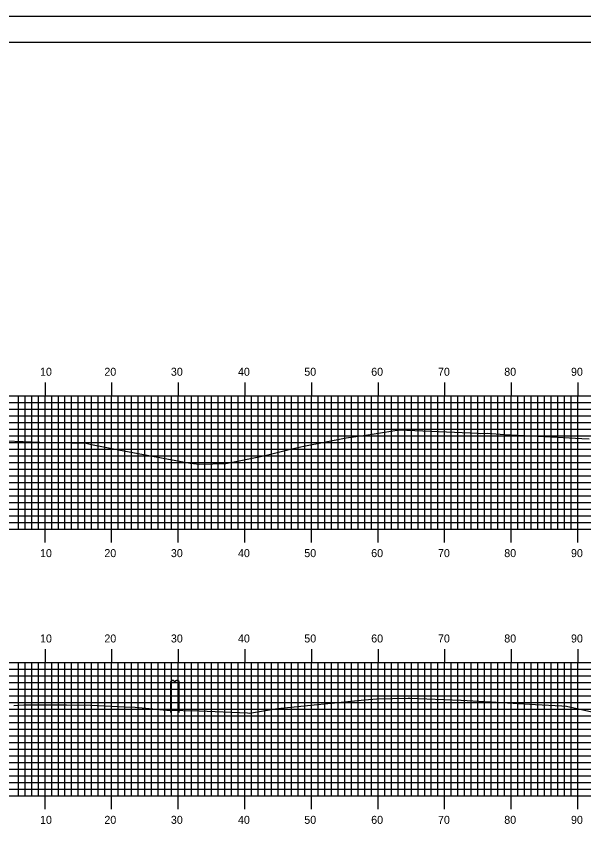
# Model space of a CAD drawing. Extents: x 855074 to 855418, y 366605 to 366825.
# Drawn here: x 855245.8 to 855330.9, y 366701.1 to 366824.9 of the extents above; entities that cross this region are included whole.
import ezdxf

# ---------------------------------------------------------------- set-up
doc = ezdxf.new("R2010")
doc.units = 0
for name, color, linetype in [('BORDER', 7, 'Continuous'), ('H_V ANNOTATION', 7, 'Continuous'), ('M_Roadway_Centerline', 7, 'Continuous'), ('MAJOR', 7, 'Continuous'), ('MINOR', 7, 'Continuous'), ('PLOT BOUNDARY', 7, 'Continuous'), ('S_Roadway_Centerline', 7, 'Continuous'), ('S_Utilities_Pole_StreetLight', 7, 'Continuous')]:
    doc.layers.add(name, color=color, linetype=linetype)

msp = doc.modelspace()

# ---------------------------------------------------------------- linework, layer by layer
at = {"layer": 'BORDER'}
msp.add_lwpolyline([(855090.47, 366611.06), (855410.47, 366611.06), (855410.47, 366821.06), (855090.47, 366821.06)], close=True, dxfattribs=at)
at = {"layer": 'MAJOR'}
for p, q in [((855250.07, 366770.06), (855250.07, 366768.06)), ((855260.07, 366770.06), (855260.07, 366768.06)), ((855270.07, 366770.06), (855270.07, 366768.06)), ((855280.07, 366770.06), (855280.07, 366768.06)), ((855290.07, 366770.06), (855290.07, 366768.06)), ((855300.07, 366770.06), (855300.07, 366768.06)), ((855310.07, 366770.06), (855310.07, 366768.06)), ((855320.07, 366770.06), (855320.07, 366768.06)), ((855330.07, 366770.06), (855330.07, 366768.06)), ((855100.07, 366768.06), (855380.07, 366768.06)), ((855100.07, 366768.06), (855380.07, 366768.06)), ((855250.07, 366748.06), (855250.07, 366768.06)), ((855260.07, 366748.06), (855260.07, 366768.06)), ((855270.07, 366748.06), (855270.07, 366768.06)), ((855280.07, 366748.06), (855280.07, 366768.06)), ((855290.07, 366748.06), (855290.07, 366768.06)), ((855300.07, 366748.06), (855300.07, 366768.06)), ((855310.07, 366748.06), (855310.07, 366768.06)), ((855320.07, 366748.06), (855320.07, 366768.06)), ((855330.07, 366748.06), (855330.07, 366768.06)), ((855100.07, 366763.06), (855380.07, 366763.06)), ((855100.07, 366758.06), (855380.07, 366758.06)), ((855100.07, 366753.06), (855380.07, 366753.06)), ((855100.07, 366748.06), (855380.07, 366748.06)), ((855100.07, 366748.06), (855380.07, 366748.06)), ((855250.07, 366746.05), (855250.07, 366748.06)), ((855260.07, 366746.05), (855260.07, 366748.06)), ((855270.07, 366746.05), (855270.07, 366748.06)), ((855280.07, 366746.05), (855280.07, 366748.06)), ((855290.07, 366746.05), (855290.07, 366748.06)), ((855300.07, 366746.05), (855300.07, 366748.06)), ((855310.07, 366746.05), (855310.07, 366748.06)), ((855320.07, 366746.05), (855320.07, 366748.06)), ((855330.07, 366746.05), (855330.07, 366748.06)), ((855250.07, 366730.06), (855250.07, 366728.06)), ((855260.07, 366730.06), (855260.07, 366728.06)), ((855270.07, 366730.06), (855270.07, 366728.06)), ((855280.07, 366730.06), (855280.07, 366728.06)), ((855290.07, 366730.06), (855290.07, 366728.06)), ((855300.07, 366730.06), (855300.07, 366728.06)), ((855310.07, 366730.06), (855310.07, 366728.06)), ((855320.07, 366730.06), (855320.07, 366728.06)), ((855330.07, 366730.06), (855330.07, 366728.06)), ((855100.07, 366728.06), (855380.07, 366728.06)), ((855100.07, 366728.06), (855380.07, 366728.06)), ((855250.07, 366708.06), (855250.07, 366728.06)), ((855260.07, 366708.06), (855260.07, 366728.06)), ((855270.07, 366708.06), (855270.07, 366728.06)), ((855280.07, 366708.06), (855280.07, 366728.06)), ((855290.07, 366708.06), (855290.07, 366728.06)), ((855300.07, 366708.06), (855300.07, 366728.06)), ((855310.07, 366708.06), (855310.07, 366728.06)), ((855320.07, 366708.06), (855320.07, 366728.06)), ((855330.07, 366708.06), (855330.07, 366728.06)), ((855100.07, 366723.06), (855380.07, 366723.06)), ((855100.07, 366718.06), (855380.07, 366718.06)), ((855100.07, 366713.06), (855380.07, 366713.06)), ((855100.07, 366708.06), (855380.07, 366708.06)), ((855100.07, 366708.06), (855380.07, 366708.06)), ((855250.07, 366706.05), (855250.07, 366708.06)), ((855260.07, 366706.05), (855260.07, 366708.06)), ((855270.07, 366706.05), (855270.07, 366708.06)), ((855280.07, 366706.05), (855280.07, 366708.06)), ((855290.07, 366706.05), (855290.07, 366708.06)), ((855300.07, 366706.05), (855300.07, 366708.06)), ((855310.07, 366706.05), (855310.07, 366708.06)), ((855320.07, 366706.05), (855320.07, 366708.06)), ((855330.07, 366706.05), (855330.07, 366708.06))]:
    msp.add_line(p, q, dxfattribs=at)
at = {"layer": 'MINOR'}
for p, q in [((855246.07, 366748.06), (855246.07, 366768.06)), ((855247.07, 366748.06), (855247.07, 366768.06)), ((855248.07, 366748.06), (855248.07, 366768.06)), ((855249.07, 366748.06), (855249.07, 366768.06)), ((855251.07, 366748.06), (855251.07, 366768.06)), ((855252.07, 366748.06), (855252.07, 366768.06)), ((855253.07, 366748.06), (855253.07, 366768.06)), ((855254.07, 366748.06), (855254.07, 366768.06)), ((855255.07, 366748.06), (855255.07, 366768.06)), ((855256.07, 366748.06), (855256.07, 366768.06)), ((855257.07, 366748.06), (855257.07, 366768.06)), ((855258.07, 366748.06), (855258.07, 366768.06)), ((855259.07, 366748.06), (855259.07, 366768.06)), ((855261.07, 366748.06), (855261.07, 366768.06)), ((855262.07, 366748.06), (855262.07, 366768.06)), ((855263.07, 366748.06), (855263.07, 366768.06)), ((855264.07, 366748.06), (855264.07, 366768.06)), ((855265.07, 366748.06), (855265.07, 366768.06)), ((855266.07, 366748.06), (855266.07, 366768.06)), ((855267.07, 366748.06), (855267.07, 366768.06)), ((855268.07, 366748.06), (855268.07, 366768.06)), ((855269.07, 366748.06), (855269.07, 366768.06)), ((855271.07, 366748.06), (855271.07, 366768.06)), ((855272.07, 366748.06), (855272.07, 366768.06)), ((855273.07, 366748.06), (855273.07, 366768.06)), ((855274.07, 366748.06), (855274.07, 366768.06)), ((855275.07, 366748.06), (855275.07, 366768.06)), ((855276.07, 366748.06), (855276.07, 366768.06)), ((855277.07, 366748.06), (855277.07, 366768.06)), ((855278.07, 366748.06), (855278.07, 366768.06)), ((855279.07, 366748.06), (855279.07, 366768.06)), ((855281.07, 366748.06), (855281.07, 366768.06)), ((855282.07, 366748.06), (855282.07, 366768.06)), ((855283.07, 366748.06), (855283.07, 366768.06)), ((855284.07, 366748.06), (855284.07, 366768.06)), ((855285.07, 366748.06), (855285.07, 366768.06)), ((855286.07, 366748.06), (855286.07, 366768.06)), ((855287.07, 366748.06), (855287.07, 366768.06)), ((855288.07, 366748.06), (855288.07, 366768.06)), ((855289.07, 366748.06), (855289.07, 366768.06)), ((855291.07, 366748.06), (855291.07, 366768.06)), ((855292.07, 366748.06), (855292.07, 366768.06)), ((855293.07, 366748.06), (855293.07, 366768.06)), ((855294.07, 366748.06), (855294.07, 366768.06)), ((855295.07, 366748.06), (855295.07, 366768.06)), ((855296.07, 366748.06), (855296.07, 366768.06)), ((855297.07, 366748.06), (855297.07, 366768.06)), ((855298.07, 366748.06), (855298.07, 366768.06)), ((855299.07, 366748.06), (855299.07, 366768.06)), ((855301.07, 366748.06), (855301.07, 366768.06)), ((855302.07, 366748.06), (855302.07, 366768.06)), ((855303.07, 366748.06), (855303.07, 366768.06)), ((855304.07, 366748.06), (855304.07, 366768.06)), ((855305.07, 366748.06), (855305.07, 366768.06)), ((855306.07, 366748.06), (855306.07, 366768.06)), ((855307.07, 366748.06), (855307.07, 366768.06)), ((855308.07, 366748.06), (855308.07, 366768.06)), ((855309.07, 366748.06), (855309.07, 366768.06)), ((855311.07, 366748.06), (855311.07, 366768.06)), ((855312.07, 366748.06), (855312.07, 366768.06)), ((855313.07, 366748.06), (855313.07, 366768.06)), ((855314.07, 366748.06), (855314.07, 366768.06)), ((855315.07, 366748.06), (855315.07, 366768.06)), ((855316.07, 366748.06), (855316.07, 366768.06)), ((855317.07, 366748.06), (855317.07, 366768.06)), ((855318.07, 366748.06), (855318.07, 366768.06)), ((855319.07, 366748.06), (855319.07, 366768.06)), ((855321.07, 366748.06), (855321.07, 366768.06)), ((855322.07, 366748.06), (855322.07, 366768.06)), ((855323.07, 366748.06), (855323.07, 366768.06)), ((855324.07, 366748.06), (855324.07, 366768.06)), ((855325.07, 366748.06), (855325.07, 366768.06)), ((855326.07, 366748.06), (855326.07, 366768.06)), ((855327.07, 366748.06), (855327.07, 366768.06)), ((855328.07, 366748.06), (855328.07, 366768.06)), ((855329.07, 366748.06), (855329.07, 366768.06)), ((855100.07, 366767.06), (855380.07, 366767.06)), ((855100.07, 366766.06), (855380.07, 366766.06)), ((855100.07, 366765.06), (855380.07, 366765.06)), ((855100.07, 366764.06), (855380.07, 366764.06)), ((855100.07, 366762.06), (855380.07, 366762.06)), ((855100.07, 366761.06), (855380.07, 366761.06)), ((855100.07, 366760.06), (855380.07, 366760.06)), ((855100.07, 366759.06), (855380.07, 366759.06)), ((855100.07, 366757.06), (855380.07, 366757.06)), ((855100.07, 366756.06), (855380.07, 366756.06)), ((855100.07, 366755.06), (855380.07, 366755.06)), ((855100.07, 366754.06), (855380.07, 366754.06)), ((855100.07, 366752.06), (855380.07, 366752.06)), ((855100.07, 366751.06), (855380.07, 366751.06)), ((855100.07, 366750.06), (855380.07, 366750.06)), ((855100.07, 366749.06), (855380.07, 366749.06)), ((855246.07, 366708.06), (855246.07, 366728.06)), ((855247.07, 366708.06), (855247.07, 366728.06)), ((855248.07, 366708.06), (855248.07, 366728.06)), ((855249.07, 366708.06), (855249.07, 366728.06)), ((855251.07, 366708.06), (855251.07, 366728.06)), ((855252.07, 366708.06), (855252.07, 366728.06)), ((855253.07, 366708.06), (855253.07, 366728.06)), ((855254.07, 366708.06), (855254.07, 366728.06)), ((855255.07, 366708.06), (855255.07, 366728.06)), ((855256.07, 366708.06), (855256.07, 366728.06)), ((855257.07, 366708.06), (855257.07, 366728.06)), ((855258.07, 366708.06), (855258.07, 366728.06)), ((855259.07, 366708.06), (855259.07, 366728.06)), ((855261.07, 366708.06), (855261.07, 366728.06)), ((855262.07, 366708.06), (855262.07, 366728.06)), ((855263.07, 366708.06), (855263.07, 366728.06)), ((855264.07, 366708.06), (855264.07, 366728.06)), ((855265.07, 366708.06), (855265.07, 366728.06)), ((855266.07, 366708.06), (855266.07, 366728.06)), ((855267.07, 366708.06), (855267.07, 366728.06)), ((855268.07, 366708.06), (855268.07, 366728.06)), ((855269.07, 366708.06), (855269.07, 366728.06)), ((855271.07, 366708.06), (855271.07, 366728.06)), ((855272.07, 366708.06), (855272.07, 366728.06)), ((855273.07, 366708.06), (855273.07, 366728.06)), ((855274.07, 366708.06), (855274.07, 366728.06)), ((855275.07, 366708.06), (855275.07, 366728.06)), ((855276.07, 366708.06), (855276.07, 366728.06)), ((855277.07, 366708.06), (855277.07, 366728.06)), ((855278.07, 366708.06), (855278.07, 366728.06)), ((855279.07, 366708.06), (855279.07, 366728.06)), ((855281.07, 366708.06), (855281.07, 366728.06)), ((855282.07, 366708.06), (855282.07, 366728.06)), ((855283.07, 366708.06), (855283.07, 366728.06)), ((855284.07, 366708.06), (855284.07, 366728.06)), ((855285.07, 366708.06), (855285.07, 366728.06)), ((855286.07, 366708.06), (855286.07, 366728.06)), ((855287.07, 366708.06), (855287.07, 366728.06)), ((855288.07, 366708.06), (855288.07, 366728.06)), ((855289.07, 366708.06), (855289.07, 366728.06)), ((855291.07, 366708.06), (855291.07, 366728.06)), ((855292.07, 366708.06), (855292.07, 366728.06)), ((855293.07, 366708.06), (855293.07, 366728.06)), ((855294.07, 366708.06), (855294.07, 366728.06)), ((855295.07, 366708.06), (855295.07, 366728.06)), ((855296.07, 366708.06), (855296.07, 366728.06)), ((855297.07, 366708.06), (855297.07, 366728.06)), ((855298.07, 366708.06), (855298.07, 366728.06)), ((855299.07, 366708.06), (855299.07, 366728.06)), ((855301.07, 366708.06), (855301.07, 366728.06)), ((855302.07, 366708.06), (855302.07, 366728.06)), ((855303.07, 366708.06), (855303.07, 366728.06)), ((855304.07, 366708.06), (855304.07, 366728.06)), ((855305.07, 366708.06), (855305.07, 366728.06)), ((855306.07, 366708.06), (855306.07, 366728.06)), ((855307.07, 366708.06), (855307.07, 366728.06)), ((855308.07, 366708.06), (855308.07, 366728.06)), ((855309.07, 366708.06), (855309.07, 366728.06)), ((855311.07, 366708.06), (855311.07, 366728.06)), ((855312.07, 366708.06), (855312.07, 366728.06)), ((855313.07, 366708.06), (855313.07, 366728.06)), ((855314.07, 366708.06), (855314.07, 366728.06)), ((855315.07, 366708.06), (855315.07, 366728.06)), ((855316.07, 366708.06), (855316.07, 366728.06)), ((855317.07, 366708.06), (855317.07, 366728.06)), ((855318.07, 366708.06), (855318.07, 366728.06)), ((855319.07, 366708.06), (855319.07, 366728.06)), ((855321.07, 366708.06), (855321.07, 366728.06)), ((855322.07, 366708.06), (855322.07, 366728.06)), ((855323.07, 366708.06), (855323.07, 366728.06)), ((855324.07, 366708.06), (855324.07, 366728.06)), ((855325.07, 366708.06), (855325.07, 366728.06)), ((855326.07, 366708.06), (855326.07, 366728.06)), ((855327.07, 366708.06), (855327.07, 366728.06)), ((855328.07, 366708.06), (855328.07, 366728.06)), ((855329.07, 366708.06), (855329.07, 366728.06)), ((855100.07, 366727.06), (855380.07, 366727.06)), ((855100.07, 366726.06), (855380.07, 366726.06)), ((855100.07, 366725.06), (855380.07, 366725.06)), ((855100.07, 366724.06), (855380.07, 366724.06)), ((855100.07, 366722.06), (855380.07, 366722.06)), ((855100.07, 366721.06), (855380.07, 366721.06)), ((855100.07, 366720.06), (855380.07, 366720.06)), ((855100.07, 366719.06), (855380.07, 366719.06)), ((855100.07, 366717.06), (855380.07, 366717.06)), ((855100.07, 366716.06), (855380.07, 366716.06)), ((855100.07, 366715.06), (855380.07, 366715.06)), ((855100.07, 366714.06), (855380.07, 366714.06)), ((855100.07, 366712.06), (855380.07, 366712.06)), ((855100.07, 366711.06), (855380.07, 366711.06)), ((855100.07, 366710.06), (855380.07, 366710.06)), ((855100.07, 366709.06), (855380.07, 366709.06))]:
    msp.add_line(p, q, dxfattribs=at)
at = {"layer": 'PLOT BOUNDARY'}
msp.add_lwpolyline([(855074.28, 366604.94), (855414.28, 366604.94), (855414.28, 366824.94), (855074.28, 366824.94)], close=True, dxfattribs=at)
at = {"layer": 'S_Roadway_Centerline'}
for points in [[(855241.7, 366761.4), (855249.3, 366761.12), (855256.25, 366760.96), (855257.04, 366760.74), (855261.92, 366759.79), (855271.84, 366757.93), (855273.3, 366757.8), (855277.21, 366757.91), (855282.91, 366759.07), (855287.15, 366760.12), (855288.92, 366760.48), (855295.29, 366761.73), (855298.24, 366762.14), (855303.23, 366762.94), (855304.39, 366762.91), (855315.12, 366762.43), (855315.41, 366762.41), (855315.42, 366762.42), (855316.56, 366762.44), (855319.02, 366762.26), (855325.09, 366761.94), (855329.73, 366761.71), (855330.67, 366761.65), (855331.75, 366761.59)], [(855245.4, 366721.61), (855246.88, 366721.73), (855247.34, 366721.71), (855253.32, 366721.7), (855256.91, 366721.67), (855261.98, 366721.43), (855263.59, 366721.36), (855268.36, 366720.9), (855273.22, 366720.81), (855280.46, 366720.49), (855280.79, 366720.44), (855284.96, 366721.14), (855298.02, 366722.44), (855299.88, 366722.62), (855304.59, 366722.7), (855304.82, 366722.71), (855312.51, 366722.41), (855312.53, 366722.43), (855316.94, 366722.17), (855323.71, 366721.77), (855327.66, 366721.56), (855328.37, 366721.53), (855340.72, 366718.76)]]:
    msp.add_lwpolyline(points, dxfattribs=at)
at = {"layer": 'S_Utilities_Pole_StreetLight'}
for p, q in [((855268.94, 366725.2), (855269.1, 366725.31)), ((855268.94, 366720.58), (855268.94, 366725.2)), ((855269.41, 366725.31), (855269.57, 366725.2)), ((855269.73, 366725.31), (855269.57, 366725.2)), ((855269.57, 366725.2), (855269.73, 366725.09)), ((855270.19, 366725.2), (855270.04, 366725.31)), ((855270.04, 366725.09), (855270.19, 366725.2)), ((855270.19, 366720.58), (855270.19, 366725.2))]:
    msp.add_line(p, q, dxfattribs=at)
for centre, start, end in [((855269.26, 366725.09), 90, 125.2644), ((855269.26, 366725.09), 54.7356, 90), ((855269.88, 366725.09), 90, 125.2644), ((855269.88, 366725.31), 234.7356, 270), ((855269.88, 366725.09), 54.7356, 90), ((855269.88, 366725.31), 270, 305.2644)]:
    msp.add_arc(centre, 0.271, start, end, dxfattribs=at)

# ---------------------------------------------------------------- texts
at = {"layer": 'H_V ANNOTATION'}
for s, p in [('10', (855249.32, 366771.06)), ('20', (855258.98, 366771.06)), ('30', (855268.97, 366771.06)), ('40', (855279.04, 366771.06)), ('50', (855289, 366771.06)), ('60', (855299.04, 366771.06)), ('70', (855309.07, 366771.06)), ('80', (855319.02, 366771.06)), ('90', (855329.04, 366771.06)), ('10', (855249.32, 366743.86)), ('20', (855258.98, 366743.86)), ('30', (855268.97, 366743.86)), ('40', (855279.04, 366743.86)), ('50', (855289, 366743.86)), ('60', (855299.04, 366743.86)), ('70', (855309.07, 366743.86)), ('80', (855319.02, 366743.86)), ('90', (855329.04, 366743.86)), ('10', (855249.32, 366731.06)), ('20', (855258.98, 366731.06)), ('30', (855268.97, 366731.06)), ('40', (855279.04, 366731.06)), ('50', (855289, 366731.06)), ('60', (855299.04, 366731.06)), ('70', (855309.07, 366731.06)), ('80', (855319.02, 366731.06)), ('90', (855329.04, 366731.06)), ('10', (855249.32, 366703.86)), ('20', (855258.98, 366703.86)), ('30', (855268.97, 366703.86)), ('40', (855279.04, 366703.86)), ('50', (855289, 366703.86)), ('60', (855299.04, 366703.86)), ('70', (855309.07, 366703.86)), ('80', (855319.02, 366703.86)), ('90', (855329.04, 366703.86))]:
    msp.add_text(s, height=1.2, dxfattribs=at).set_placement(p)
at = {"layer": 'M_Roadway_Centerline'}
for s, p in [('C', (855316.55, 366762.44)), ('L', (855316.56, 366762.43)), ('C', (855246.87, 366721.73)), ('C', (855312.53, 366722.43)), ('L', (855312.53, 366722.43)), ('L', (855246.88, 366721.72))]:
    msp.add_text(s, height=0.0146, dxfattribs=at).set_placement(p)

doc.saveas('drawing.dxf')
